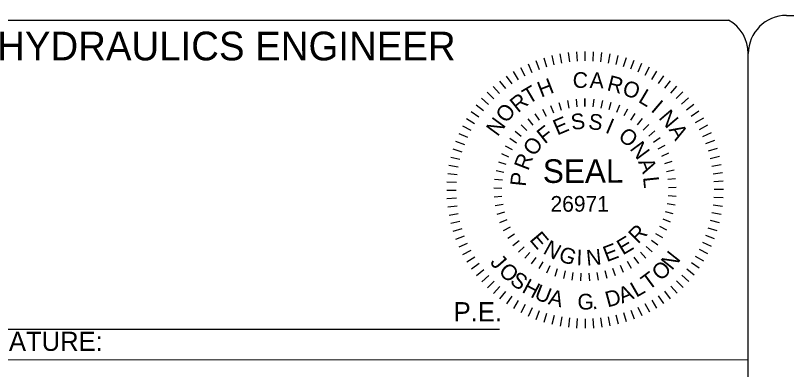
# Model space of a CAD drawing. Extents: x 2105791 to 2114488, y 667759 to 673441.
# Drawn here: x 2112480 to 2113520, y 668366 to 668844 of the extents above; entities that cross this region are included whole.
import ezdxf

# ---------------------------------------------------------------- set-up
doc = ezdxf.new("R2010")
doc.units = 0
doc.layers.add('Default', color=7, linetype='Continuous')
doc.layers.add('Sheet Title CELL', color=7, linetype='Continuous')

msp = doc.modelspace()

# ---------------------------------------------------------------- linework, layer by layer
at = {"layer": 'Default'}
for p, q in [((2113214.3, 668792), (2113216.6, 668779.5)), ((2113225.4, 668793.7), (2113227, 668781.1)), ((2113236.6, 668794.8), (2113237.4, 668782.1)), ((2113247.9, 668795.1), (2113247.9, 668782.4)), ((2113259.2, 668794.8), (2113258.5, 668782.1)), ((2113270.4, 668793.8), (2113268.9, 668781.2)), ((2113281.6, 668792.1), (2113279.3, 668779.6)), ((2113292.6, 668789.8), (2113289.6, 668777.4)), ((2113181.7, 668782.9), (2113186.3, 668771)), ((2113192.4, 668786.6), (2113196.2, 668774.4)), ((2113203.3, 668789.6), (2113206.3, 668777.3)), ((2113303.5, 668786.8), (2113299.7, 668774.6)), ((2113314.2, 668783.1), (2113309.7, 668771.2)), ((2113161.2, 668773.6), (2113167.1, 668762.3)), ((2113171.3, 668778.5), (2113176.6, 668766.9)), ((2113324.6, 668778.8), (2113319.4, 668767.2)), ((2113334.7, 668773.9), (2113328.8, 668762.6)), ((2113141.9, 668761.9), (2113149.2, 668751.4)), ((2113151.4, 668768), (2113158, 668757.1)), ((2113344.6, 668768.4), (2113338, 668757.5)), ((2113354.1, 668762.3), (2113346.9, 668751.8)), ((2113132.9, 668755.2), (2113140.7, 668745.2)), ((2113363.1, 668755.6), (2113355.3, 668745.6)), ((2113371.8, 668748.4), (2113363.4, 668738.9)), ((2113116, 668740.2), (2113125, 668731.2)), ((2113124.2, 668747.9), (2113132.6, 668738.4)), ((2113380.1, 668740.7), (2113371.1, 668731.7)), ((2113108.3, 668732), (2113117.8, 668723.5)), ((2113224.4, 668729.1), (2113226.5, 668718.7)), ((2113236.2, 668730.9), (2113237.2, 668720.3)), ((2113248, 668731.5), (2113248.1, 668720.9)), ((2113248.1, 668720.9), (2113248, 668731.5)), ((2113259.9, 668730.9), (2113258.9, 668720.4)), ((2113271.7, 668729.2), (2113269.7, 668718.8)), ((2113387.8, 668732.5), (2113378.3, 668724)), ((2113101.1, 668723.3), (2113111.1, 668715.4)), ((2113190.9, 668717.3), (2113195.8, 668707.9)), ((2113201.7, 668722.3), (2113205.7, 668712.5)), ((2113212.9, 668726.3), (2113215.9, 668716.1)), ((2113283.2, 668726.4), (2113280.2, 668716.2)), ((2113294.5, 668722.5), (2113290.5, 668712.6)), ((2113305.3, 668717.5), (2113300.4, 668708.1)), ((2113395.1, 668723.8), (2113385, 668716)), ((2113094.4, 668714.2), (2113104.9, 668707)), ((2113180.6, 668711.2), (2113186.5, 668702.3)), ((2113315.5, 668711.5), (2113309.7, 668702.6)), ((2113401.7, 668714.8), (2113391.3, 668707.5)), ((2113088.3, 668704.7), (2113099.2, 668698.1)), ((2113162.2, 668696.3), (2113169.6, 668688.7)), ((2113171, 668704.2), (2113177.7, 668695.9)), ((2113325.2, 668704.5), (2113318.5, 668696.2)), ((2113334.1, 668696.6), (2113326.7, 668689)), ((2113407.9, 668705.3), (2113397, 668698.7)), ((2113082.8, 668694.9), (2113094.1, 668689)), ((2113154.1, 668687.6), (2113162.2, 668680.8)), ((2113342.2, 668687.9), (2113334.1, 668681.1)), ((2113413.5, 668695.5), (2113402.2, 668689.5)), ((2113077.9, 668684.7), (2113089.5, 668679.5)), ((2113146.9, 668678.1), (2113155.6, 668672.1)), ((2113349.4, 668678.5), (2113340.7, 668672.4)), ((2113418.4, 668685.3), (2113406.8, 668680.1)), ((2113073.6, 668674.3), (2113085.5, 668669.8)), ((2113140.6, 668668), (2113149.9, 668662.9)), ((2113355.7, 668668.4), (2113346.5, 668663.2)), ((2113422.8, 668674.9), (2113410.9, 668670.4)), ((2113069.9, 668663.6), (2113082.1, 668659.9)), ((2113135.4, 668657.3), (2113145.1, 668653.1)), ((2113361, 668657.8), (2113351.3, 668653.5)), ((2113426.5, 668664.3), (2113414.3, 668660.5)), ((2113066.9, 668652.7), (2113079.3, 668649.7)), ((2113131.2, 668646.2), (2113141.3, 668643)), ((2113365.2, 668646.6), (2113355.2, 668643.4)), ((2113429.5, 668653.4), (2113417.1, 668650.4)), ((2113064.5, 668641.7), (2113077.1, 668639.4)), ((2113128.1, 668634.7), (2113138.4, 668632.5)), ((2113368.4, 668635.2), (2113358, 668632.9)), ((2113431.9, 668642.4), (2113419.4, 668640.1)), ((2113062.9, 668630.6), (2113075.5, 668629.1)), ((2113370.4, 668623.5), (2113359.9, 668622.2)), ((2113433.6, 668631.3), (2113421, 668629.7)), ((2113061.9, 668619.3), (2113074.6, 668618.6)), ((2113126.1, 668623), (2113136.6, 668621.8)), ((2113434.6, 668620), (2113421.9, 668619.2)), ((2113061.6, 668608), (2113074.3, 668608.1)), ((2113125.2, 668611.1), (2113135.8, 668610.9)), ((2113371.3, 668611.6), (2113360.7, 668611.3)), ((2113435, 668608.7), (2113422.3, 668608.7)), ((2113061.9, 668596.8), (2113074.6, 668597.5)), ((2113125.5, 668599.2), (2113136.1, 668600)), ((2113371, 668599.7), (2113360.5, 668600.5)), ((2113434.7, 668597.5), (2113422, 668598.2)), ((2113063, 668585.5), (2113075.6, 668587.1)), ((2113127, 668587.4), (2113137.5, 668589.3)), ((2113359.2, 668590), (2113369.7, 668588.3)), ((2113433.7, 668586.2), (2113421.1, 668587.7)), ((2113064.7, 668574.4), (2113077.2, 668576.7)), ((2113129.6, 668575.8), (2113139.8, 668578.6)), ((2113367.1, 668576.3), (2113356.9, 668579)), ((2113432, 668575.1), (2113419.5, 668577.3)), ((2113067.1, 668563.4), (2113079.4, 668566.4)), ((2113133.3, 668564.5), (2113143.2, 668568.3)), ((2113363.4, 668565), (2113353.5, 668568.7)), ((2113429.7, 668564.1), (2113417.3, 668567.1)), ((2113070.1, 668552.5), (2113082.3, 668556.3)), ((2113138.1, 668553.6), (2113147.6, 668558.4)), ((2113358.7, 668554.1), (2113349.2, 668558.8)), ((2113426.7, 668553.2), (2113414.5, 668556.9)), ((2113073.8, 668541.9), (2113085.7, 668546.4)), ((2113143.9, 668543.3), (2113152.9, 668548.9)), ((2113346.2, 668533.8), (2113337.8, 668540.3)), ((2113353, 668543.7), (2113343.9, 668549.2)), ((2113423, 668542.5), (2113411.1, 668547)), ((2113078.2, 668531.4), (2113089.7, 668536.7)), ((2113150.6, 668533.5), (2113159.1, 668539.9)), ((2113158.3, 668524.4), (2113166.1, 668531.6)), ((2113338.6, 668524.8), (2113330.8, 668532)), ((2113418.7, 668532.1), (2113407.1, 668537.3)), ((2113083.1, 668521.3), (2113094.4, 668527.2)), ((2113166.8, 668516.1), (2113173.9, 668524.1)), ((2113330.1, 668516.4), (2113323, 668524.4)), ((2113413.8, 668521.9), (2113402.5, 668527.8)), ((2113088.7, 668511.5), (2113099.5, 668518.1)), ((2113094.8, 668502), (2113105.3, 668509.3)), ((2113176.1, 668508.7), (2113182.3, 668517.3)), ((2113186.1, 668502.2), (2113191.5, 668511.4)), ((2113310.9, 668502.4), (2113305.5, 668511.6)), ((2113320.8, 668509), (2113314.6, 668517.5)), ((2113402.2, 668502.6), (2113391.7, 668509.8)), ((2113408.3, 668512.1), (2113397.4, 668518.7)), ((2113101.5, 668493), (2113111.5, 668500.8)), ((2113196.6, 668496.7), (2113201.1, 668506.3)), ((2113207.7, 668492.2), (2113211.2, 668502.2)), ((2113221.5, 668499.2), (2113219, 668488.9)), ((2113278, 668489), (2113275.4, 668499.3)), ((2113289.3, 668492.4), (2113285.8, 668502.4)), ((2113300.3, 668496.9), (2113295.9, 668506.5)), ((2113395.5, 668493.5), (2113385.5, 668501.3)), ((2113108.8, 668484.3), (2113118.3, 668492.8)), ((2113230.7, 668486.6), (2113232.2, 668497.1)), ((2113242.6, 668485.5), (2113243, 668496.1)), ((2113254.5, 668485.5), (2113253.9, 668496.1)), ((2113266.3, 668486.7), (2113264.7, 668497.1)), ((2113388.3, 668484.8), (2113378.7, 668493.3)), ((2113116.5, 668476.1), (2113125.5, 668485.1)), ((2113124.7, 668468.4), (2113133.1, 668477.9)), ((2113372.4, 668468.9), (2113363.9, 668478.4)), ((2113380.6, 668476.6), (2113371.5, 668485.6)), ((2113133.4, 668461.2), (2113141.2, 668471.2)), ((2113363.7, 668461.6), (2113355.8, 668471.6)), ((2113142.5, 668454.5), (2113149.7, 668465)), ((2113152, 668448.4), (2113158.5, 668459.3)), ((2113345.2, 668448.8), (2113338.6, 668459.7)), ((2113354.6, 668454.9), (2113347.4, 668465.4)), ((2113161.8, 668442.9), (2113167.7, 668454.2)), ((2113172, 668438), (2113177.2, 668449.6)), ((2113325.2, 668438.3), (2113320, 668449.9)), ((2113335.4, 668443.2), (2113329.4, 668454.5)), ((2113182.4, 668433.7), (2113186.9, 668445.6)), ((2113193.1, 668430), (2113196.8, 668442.2)), ((2113203.9, 668427), (2113206.9, 668439.4)), ((2113215, 668424.7), (2113217.2, 668437.2)), ((2113282.3, 668424.8), (2113280, 668437.3)), ((2113293.3, 668427.2), (2113290.2, 668439.5)), ((2113304.2, 668430.2), (2113300.4, 668442.4)), ((2113314.8, 668433.9), (2113310.3, 668445.8)), ((2113226.1, 668423), (2113227.6, 668435.6)), ((2113237.3, 668422), (2113238.1, 668434.7)), ((2113248.6, 668421.7), (2113248.6, 668434.4)), ((2113259.9, 668422), (2113259.1, 668434.7)), ((2113271.1, 668423.1), (2113269.6, 668435.7))]:
    msp.add_line(p, q, dxfattribs=at)
at = {"layer": 'Sheet Title CELL'}
for p, q in [((2113520.1, 668843.8), (2114321.7, 668843.7)), ((2112384.6, 668837.6), (2113441.8, 668837.4)), ((2113468.4, 667966), (2113468.5, 668792.2)), ((2113468.4, 667966), (2113468.5, 668792.2)), ((2112387.8, 668420.6), (2113132.7, 668420.5)), ((2112353.8, 668379.4), (2113468.4, 668379.2))]:
    msp.add_line(p, q, dxfattribs=at)
for centre, start, end in [((2113520.1, 668792.2), 89.9903, 179.9903), ((2113520.1, 668792.2), 89.9903, 179.9903), ((2113416.9, 668792.2), 359.9903, 61.0741)]:
    msp.add_arc(centre, 51.6, start, end, dxfattribs=at)

# ---------------------------------------------------------------- texts
at = {"layer": 'Default'}
for s, height, rotation, p in [('H', 21.2, 21.1759, (2113188.9, 668732.8)), ('C', 21.2, 357.4652, (2113231.1, 668746.5)), ('A', 21.2, 357.4652, (2113254.2, 668746.1)), ('R', 21.2, 345.4559, (2113276.7, 668743)), ('T', 21.2, 30.6078, (2113171.9, 668723.5)), ('O', 21.2, 342.3991, (2113297.2, 668737)), ('L', 21.2, 329.2628, (2113318.8, 668727.6)), ('R', 21.2, 38.7688, (2113157.6, 668711.6)), ('I', 21.2, 319.6873, (2113335.9, 668715.3)), ('O', 21.2, 51.8255, (2113142.3, 668697.3)), ('N', 21.2, 310.3929, (2113346.6, 668705.3)), ('N', 21.2, 53.785, (2113130.2, 668679.4)), ('E', 21.2, 23.0526, (2113210.7, 668681.6)), ('S', 21.2, 7.7563, (2113230.6, 668689)), ('S', 21.2, 352.4601, (2113251.8, 668690.8)), ('F', 21.2, 38.3488, (2113193.8, 668669.6)), ('I', 21.2, 337.1639, (2113274.3, 668686.2)), ('O', 21.2, 321.8676, (2113291.5, 668678)), ('A', 21.2, 300.6253, (2113360.6, 668689.7)), ('O', 21.2, 53.6451, (2113179.7, 668652.5)), ('N', 21.2, 306.5714, (2113307.8, 668663.8)), ('R', 21.2, 68.9413, (2113171.4, 668633.4)), ('SEAL', 31.82, 0.1082, (2113191.3, 668617.8)), ('A', 21.2, 291.2751, (2113319.5, 668646.5)), ('P', 21.2, 84.2376, (2113168.2, 668612.4)), ('L', 21.2, 275.9789, (2113326.4, 668625.5)), ('26971', 21.19, 0.1082, (2113201.6, 668578.9)), ('E', 21.2, 310.1783, (2113172.4, 668540.9)), ('R', 21.2, 44.6731, (2113319.4, 668534.7)), ('N', 21.2, 331.0334, (2113190.3, 668523.3)), ('E', 21.2, 30.902, (2113299.2, 668519.8)), ('G', 21.2, 339.7996, (2113211, 668513.4)), ('E', 21.2, 20.9161, (2113277.5, 668510.8)), ('J', 21.2, 310.9673, (2113119.1, 668510.1)), ('I', 21.2, 357.8944, (2113236.3, 668506.7)), ('N', 21.2, 5.5241, (2113250.7, 668506)), ('N', 21.2, 51.4058, (2113365.5, 668498.9)), ('O', 21.2, 44.0013, (2113350.5, 668484.5)), ('O', 21.2, 317.1776, (2113130.3, 668496.8)), ('T', 21.2, 36.5968, (2113333.9, 668472.2)), ('S', 21.2, 324.5821, (2113145.5, 668482.7)), ('H', 21.2, 331.7477, (2113161.8, 668471)), ('U', 21.2, 338.5551, (2113178.5, 668461.9)), ('A', 21.2, 22.3849, (2113298.1, 668454.9)), ('L', 21.2, 29.7894, (2113317.3, 668462.8)), ('A', 21.2, 345.8401, (2113197.5, 668454.4)), ('G', 21.2, 0.6492, (2113238.1, 668446.8)), ('D', 21.2, 15.2193, (2113278.7, 668449.7)), ('.', 21.2, 7.8148, (2113258.2, 668447))]:
    msp.add_text(s, height=height, rotation=rotation, dxfattribs=at).set_placement(p)
at = {"layer": 'Sheet Title CELL'}
for s, height, p in [(' HYDRAULICS ENGINEER', 38.728, (2112440.5, 668783.2)), ('P.E.', 25.82, (2113070.9, 668431.1)), ('SIGNATURE:', 25.82, (2112386.4, 668391.2))]:
    msp.add_text(s, height=height, rotation=359.9903, dxfattribs=at).set_placement(p)

doc.saveas('drawing.dxf')
